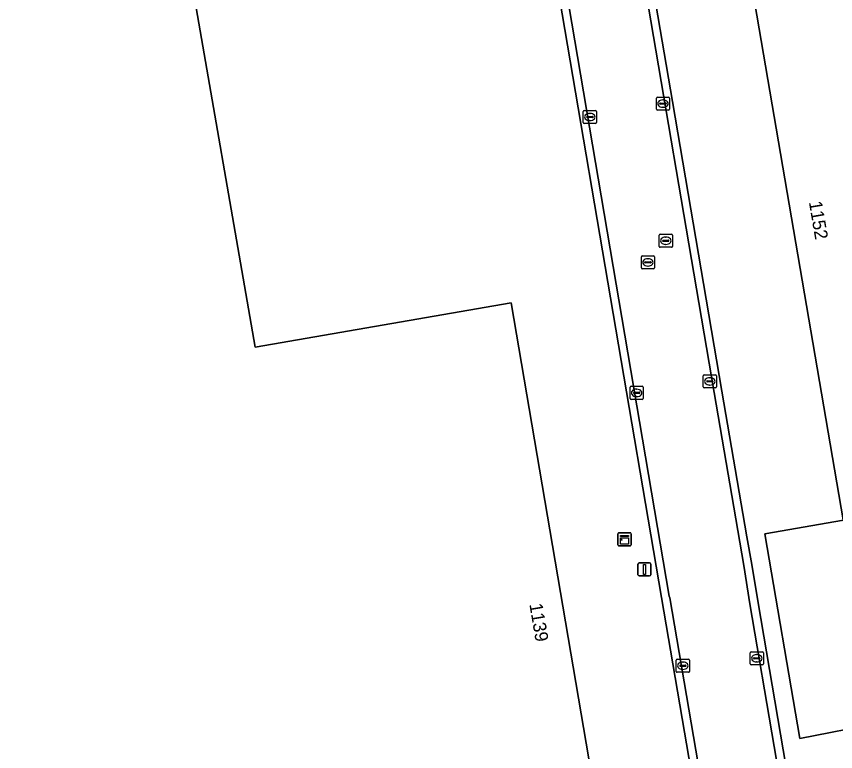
# Model space of a CAD drawing. Extents: x 154324 to 155744, y 382937 to 384188.
# Drawn here: x 154819.6 to 154882.3, y 383713.4 to 383769.7 of the extents above; entities that cross this region are included whole.
import ezdxf

# ---------------------------------------------------------------- set-up
doc = ezdxf.new("R2010")
doc.units = 0
for name, color, linetype in [('IMGEO_Kast', 7, 'Continuous'), ('IMGEO_Kolk', 7, 'Continuous'), ('IMGEO_Lichtmast', 7, 'Continuous'), ('IMGEO_Pand', 7, 'Continuous'), ('IMGEO_Pand_nummerreeks', 7, 'Continuous'), ('IMGEO_Parkeervlak_open', 7, 'Continuous'), ('IMGEO_Rijbaan_lokaal_gesloten', 7, 'Continuous'), ('IMGEO_Rijbaan_lokaal_open', 7, 'Continuous'), ('IMGEO_Rioolput', 7, 'Continuous'), ('IMGEO_Voetpad_open', 7, 'Continuous')]:
    doc.layers.add(name, color=color, linetype=linetype)

msp = doc.modelspace()

# ---------------------------------------------------------------- linework, layer by layer
at = {"layer": 'IMGEO_Kast'}
for p, q in [((154865.711, 383730.124), (154866.552, 383730.124)), ((154866.552, 383730.124), (154865.711, 383730.124)), ((154865.636, 383729.199), (154865.636, 383730.04)), ((154865.636, 383730.04), (154865.636, 383729.199)), ((154866.636, 383730.049), (154866.636, 383729.208)), ((154866.636, 383729.208), (154866.636, 383730.049)), ((154866.561, 383729.124), (154865.72, 383729.124)), ((154865.72, 383729.124), (154866.561, 383729.124))]:
    msp.add_line(p, q, dxfattribs=at)
for points in [[(154865.831, 383729.914), (154866.431, 383729.914), (154866.431, 383729.829), (154865.831, 383729.829), (154865.831, 383729.914)], [(154865.831, 383729.739), (154866.431, 383729.739), (154866.431, 383729.25), (154865.831, 383729.25), (154865.831, 383729.739)]]:
    msp.add_lwpolyline(points, dxfattribs=at)
msp.add_circle((154865.915, 383729.588), 0.0377, dxfattribs=at)
for centre, start, end in [((154865.714, 383730.046), 92.4484, 184.28452), ((154865.714, 383730.046), 92.4484, 184.28452), ((154866.558, 383730.046), 2.4484, 94.28452), ((154866.558, 383730.046), 2.4484, 94.28452), ((154865.714, 383729.202), 182.4484, 274.28452), ((154865.714, 383729.202), 182.4484, 274.28452), ((154866.558, 383729.202), 272.4484, 4.28452), ((154866.558, 383729.202), 272.4484, 4.28452)]:
    msp.add_arc(centre, 0.0779, start, end, dxfattribs=at)
at = {"layer": 'IMGEO_Kolk'}
for p, q in [((154868.575, 383762.549), (154868.575, 383763.401)), ((154868.65, 383763.475), (154869.502, 383763.475)), ((154869.576, 383763.401), (154869.576, 383762.549)), ((154868.834, 383762.969), (154868.834, 383762.981)), ((154869.272, 383762.932), (154868.874, 383762.932)), ((154868.877, 383763.018), (154869.275, 383763.018)), ((154869.086, 383762.695), (154869.061, 383762.695)), ((154869.063, 383763.255), (154869.088, 383763.255)), ((154869.318, 383762.981), (154869.318, 383762.969)), ((154862.984, 383761.524), (154862.984, 383762.376)), ((154863.059, 383762.45), (154863.911, 383762.45)), ((154863.472, 383762.23), (154863.497, 383762.23)), ((154863.985, 383762.376), (154863.985, 383761.524)), ((154869.502, 383762.475), (154868.65, 383762.475)), ((154863.911, 383761.45), (154863.059, 383761.45)), ((154863.243, 383761.944), (154863.243, 383761.956)), ((154863.681, 383761.907), (154863.283, 383761.907)), ((154863.286, 383761.993), (154863.684, 383761.993)), ((154863.495, 383761.67), (154863.47, 383761.67)), ((154863.727, 383761.956), (154863.727, 383761.944)), ((154872.164, 383741.281), (154872.164, 383742.133)), ((154872.239, 383742.207), (154873.091, 383742.207)), ((154872.652, 383741.987), (154872.677, 383741.987)), ((154873.165, 383742.133), (154873.165, 383741.281)), ((154872.423, 383741.701), (154872.423, 383741.713)), ((154872.861, 383741.664), (154872.463, 383741.664)), ((154872.466, 383741.75), (154872.864, 383741.75)), ((154872.675, 383741.427), (154872.65, 383741.427)), ((154872.907, 383741.713), (154872.907, 383741.701)), ((154866.57, 383740.405), (154866.57, 383741.257)), ((154866.645, 383741.331), (154867.497, 383741.331)), ((154866.829, 383740.825), (154866.829, 383740.837)), ((154867.267, 383740.788), (154866.869, 383740.788)), ((154866.872, 383740.874), (154867.27, 383740.874)), ((154867.058, 383741.111), (154867.083, 383741.111)), ((154867.313, 383740.837), (154867.313, 383740.825)), ((154867.571, 383741.257), (154867.571, 383740.405)), ((154873.091, 383741.207), (154872.239, 383741.207)), ((154867.497, 383740.331), (154866.645, 383740.331)), ((154867.081, 383740.551), (154867.056, 383740.551)), ((154875.756, 383720.087), (154875.756, 383720.939)), ((154875.831, 383721.013), (154876.683, 383721.013)), ((154876.244, 383720.793), (154876.269, 383720.793)), ((154876.757, 383720.939), (154876.757, 383720.087)), ((154870.098, 383719.512), (154870.098, 383720.364)), ((154870.173, 383720.438), (154871.025, 383720.438)), ((154870.586, 383720.218), (154870.611, 383720.218)), ((154871.099, 383720.364), (154871.099, 383719.512)), ((154876.015, 383720.507), (154876.015, 383720.519)), ((154876.453, 383720.47), (154876.055, 383720.47)), ((154876.058, 383720.556), (154876.456, 383720.556)), ((154876.267, 383720.233), (154876.242, 383720.233)), ((154876.499, 383720.519), (154876.499, 383720.507)), ((154871.025, 383719.438), (154870.173, 383719.438)), ((154870.357, 383719.932), (154870.357, 383719.944)), ((154870.795, 383719.895), (154870.397, 383719.895)), ((154870.4, 383719.981), (154870.798, 383719.981)), ((154870.609, 383719.658), (154870.584, 383719.658)), ((154870.841, 383719.944), (154870.841, 383719.932)), ((154876.683, 383720.013), (154875.831, 383720.013))]:
    msp.add_line(p, q, dxfattribs=at)
for points in [[(154868.575, 383762.549), (154868.575, 383763.401)], [(154868.65, 383763.475), (154869.502, 383763.475)], [(154869.576, 383763.401), (154869.576, 383762.549)], [(154862.984, 383761.524), (154862.984, 383762.376)], [(154863.059, 383762.45), (154863.911, 383762.45)], [(154863.985, 383762.376), (154863.985, 383761.524)], [(154869.502, 383762.475), (154868.65, 383762.475)], [(154863.911, 383761.45), (154863.059, 383761.45)], [(154872.164, 383741.281), (154872.164, 383742.133)], [(154872.239, 383742.207), (154873.091, 383742.207)], [(154873.165, 383742.133), (154873.165, 383741.281)], [(154866.57, 383740.405), (154866.57, 383741.257)], [(154866.645, 383741.331), (154867.497, 383741.331)], [(154867.571, 383741.257), (154867.571, 383740.405)], [(154873.091, 383741.207), (154872.239, 383741.207)], [(154867.497, 383740.331), (154866.645, 383740.331)], [(154875.756, 383720.087), (154875.756, 383720.939)], [(154875.831, 383721.013), (154876.683, 383721.013)], [(154876.757, 383720.939), (154876.757, 383720.087)], [(154870.098, 383719.512), (154870.098, 383720.364)], [(154870.173, 383720.438), (154871.025, 383720.438)], [(154871.099, 383720.364), (154871.099, 383719.512)], [(154871.025, 383719.438), (154870.173, 383719.438)], [(154876.683, 383720.013), (154875.831, 383720.013)]]:
    msp.add_lwpolyline(points, dxfattribs=at)
for centre, radius, start, end in [((154868.652, 383763.399), 0.0765, 91.55205, 178.44795), ((154868.652, 383763.399), 0.0765, 91.55205, 178.44795), ((154869.5, 383763.399), 0.0765, 1.55205, 88.44795), ((154869.5, 383763.399), 0.0765, 1.55205, 88.44795), ((154868.874, 383762.978), 0.0403, 85.87752, 175.75265), ((154868.871, 383762.968), 0.0366, 178.93798, 274.71019), ((154869.275, 383762.975), 0.043, 264.86636, 352.45326), ((154869.279, 383762.98), 0.0386, 1.73085, 96.63898), ((154863.061, 383762.374), 0.0765, 91.55205, 178.44795), ((154863.061, 383762.374), 0.0765, 91.55205, 178.44795), ((154863.909, 383762.374), 0.0765, 1.55205, 88.44795), ((154863.909, 383762.374), 0.0765, 1.55205, 88.44795), ((154868.652, 383762.551), 0.0765, 181.55205, 268.44795), ((154868.652, 383762.551), 0.0765, 181.55205, 268.44795), ((154869.5, 383762.551), 0.0765, 271.55205, 358.44795), ((154869.5, 383762.551), 0.0765, 271.55205, 358.44795), ((154863.061, 383761.526), 0.0765, 181.55205, 268.44795), ((154863.061, 383761.526), 0.0765, 181.55205, 268.44795), ((154863.283, 383761.953), 0.0403, 85.87752, 175.75265), ((154863.28, 383761.943), 0.0366, 178.93798, 274.71019), ((154863.684, 383761.95), 0.043, 264.86636, 352.45326), ((154863.688, 383761.955), 0.0386, 1.73085, 96.63898), ((154863.909, 383761.526), 0.0765, 271.55205, 358.44795), ((154863.909, 383761.526), 0.0765, 271.55205, 358.44795), ((154872.241, 383742.131), 0.0765, 91.55205, 178.44795), ((154872.241, 383742.131), 0.0765, 91.55205, 178.44795), ((154873.089, 383742.131), 0.0765, 1.55205, 88.44795), ((154873.089, 383742.131), 0.0765, 1.55205, 88.44795), ((154872.463, 383741.71), 0.0403, 85.87752, 175.75265), ((154872.46, 383741.7), 0.0366, 178.93798, 274.71019), ((154872.864, 383741.707), 0.043, 264.86636, 352.45326), ((154872.868, 383741.712), 0.0386, 1.73085, 96.63898), ((154866.647, 383741.255), 0.0765, 91.55205, 178.44795), ((154866.647, 383741.255), 0.0765, 91.55205, 178.44795), ((154866.869, 383740.834), 0.0403, 85.87752, 175.75265), ((154866.866, 383740.824), 0.0366, 178.93798, 274.71019), ((154867.27, 383740.831), 0.043, 264.86636, 352.45326), ((154867.274, 383740.836), 0.0386, 1.73085, 96.63898), ((154867.495, 383741.255), 0.0765, 1.55205, 88.44795), ((154867.495, 383741.255), 0.0765, 1.55205, 88.44795), ((154872.241, 383741.283), 0.0765, 181.55205, 268.44795), ((154872.241, 383741.283), 0.0765, 181.55205, 268.44795), ((154873.089, 383741.283), 0.0765, 271.55205, 358.44795), ((154873.089, 383741.283), 0.0765, 271.55205, 358.44795), ((154866.647, 383740.407), 0.0765, 181.55205, 268.44795), ((154866.647, 383740.407), 0.0765, 181.55205, 268.44795), ((154867.495, 383740.407), 0.0765, 271.55205, 358.44795), ((154867.495, 383740.407), 0.0765, 271.55205, 358.44795), ((154875.833, 383720.937), 0.0765, 91.55205, 178.44795), ((154875.833, 383720.937), 0.0765, 91.55205, 178.44795), ((154876.681, 383720.937), 0.0765, 1.55205, 88.44795), ((154876.681, 383720.937), 0.0765, 1.55205, 88.44795), ((154870.175, 383720.362), 0.0765, 91.55205, 178.44795), ((154870.175, 383720.362), 0.0765, 91.55205, 178.44795), ((154871.023, 383720.362), 0.0765, 1.55205, 88.44795), ((154871.023, 383720.362), 0.0765, 1.55205, 88.44795), ((154875.833, 383720.089), 0.0765, 181.55205, 268.44795), ((154875.833, 383720.089), 0.0765, 181.55205, 268.44795), ((154876.055, 383720.516), 0.0403, 85.87752, 175.75265), ((154876.052, 383720.506), 0.0366, 178.93798, 274.71019), ((154876.456, 383720.513), 0.043, 264.86636, 352.45326), ((154876.46, 383720.518), 0.0386, 1.73085, 96.63898), ((154876.681, 383720.089), 0.0765, 271.55205, 358.44795), ((154876.681, 383720.089), 0.0765, 271.55205, 358.44795), ((154870.175, 383719.514), 0.0765, 181.55205, 268.44795), ((154870.175, 383719.514), 0.0765, 181.55205, 268.44795), ((154870.397, 383719.941), 0.0403, 85.87752, 175.75265), ((154870.394, 383719.931), 0.0366, 178.93798, 274.71019), ((154870.798, 383719.938), 0.043, 264.86636, 352.45326), ((154870.802, 383719.943), 0.0386, 1.73085, 96.63898), ((154871.023, 383719.514), 0.0765, 271.55205, 358.44795), ((154871.023, 383719.514), 0.0765, 271.55205, 358.44795)]:
    msp.add_arc(centre, radius, start, end, dxfattribs=at)
for centre, major_axis, ratio, start_param, end_param in [((154869.062, 383762.975), (-0.387, 0.002), 0.722429, 4.712389, 7.853982), ((154869.087, 383762.975), (-0.39, 0.002), 0.717154, 1.570796, 4.712389), ((154863.471, 383761.95), (-0.387, 0.002), 0.722429, 4.712389, 7.853982), ((154863.496, 383761.95), (-0.39, 0.002), 0.717154, 1.570796, 4.712389), ((154872.651, 383741.707), (-0.387, 0.002), 0.722429, 4.712389, 7.853982), ((154872.676, 383741.707), (-0.39, 0.002), 0.717154, 1.570796, 4.712389), ((154867.057, 383740.831), (-0.387, 0.002), 0.722429, 4.712389, 7.853982), ((154867.082, 383740.831), (-0.39, 0.002), 0.717154, 1.570796, 4.712389), ((154876.243, 383720.513), (-0.387, 0.002), 0.722429, 4.712389, 7.853982), ((154876.268, 383720.513), (-0.39, 0.002), 0.717154, 1.570796, 4.712389), ((154870.585, 383719.938), (-0.387, 0.002), 0.722429, 4.712389, 7.853982), ((154870.61, 383719.938), (-0.39, 0.002), 0.717154, 1.570796, 4.712389)]:
    msp.add_ellipse(centre, major_axis=major_axis, ratio=ratio, start_param=start_param, end_param=end_param, dxfattribs=at)
at = {"layer": 'IMGEO_Lichtmast'}
for p, q in [((154867.168, 383726.911), (154867.168, 383727.711)), ((154867.168, 383727.711), (154867.168, 383726.911)), ((154867.268, 383727.811), (154868.058, 383727.811)), ((154868.058, 383727.811), (154867.268, 383727.811)), ((154868.158, 383727.711), (154868.158, 383726.911)), ((154868.158, 383726.911), (154868.158, 383727.711)), ((154868.058, 383726.811), (154867.268, 383726.811)), ((154867.268, 383726.811), (154868.058, 383726.811))]:
    msp.add_line(p, q, dxfattribs=at)
msp.add_lwpolyline([(154867.588, 383727.686), (154867.738, 383727.686), (154867.738, 383726.936), (154867.588, 383726.936), (154867.588, 383727.686)], dxfattribs=at)
for centre, start, end in [((154867.268, 383727.711), 90, 180), ((154867.268, 383727.711), 90, 180), ((154868.058, 383727.711), 0, 90), ((154868.058, 383727.711), 360, 90), ((154867.268, 383726.911), 180, 270), ((154867.268, 383726.911), 180, 270), ((154868.058, 383726.911), 270, 0), ((154868.058, 383726.911), 270, 0)]:
    msp.add_arc(centre, 0.1, start, end, dxfattribs=at)
at = {"layer": 'IMGEO_Pand'}
for points in [[(154837.735, 383816.061), (154769.16, 383784.679), (154787.882, 383674.892), (154867.567, 383688.391), (154857.459, 383747.727), (154837.877, 383744.339)], [(154837.877, 383744.339), (154832.77, 383773.851), (154852.427, 383777.261), (154848.68, 383799.111), (154846.651, 383810.938)]]:
    msp.add_lwpolyline(points, dxfattribs=at)
msp.add_lwpolyline([(154925.991, 383785.242), (154875.097, 383776.585), (154875.115, 383776.481), (154882.872, 383731.113), (154904.981, 383734.884), (154933.724, 383739.787)], close=True, dxfattribs=at)
at = {"layer": 'IMGEO_Parkeervlak_open'}
msp.add_lwpolyline([(154846.651, 383810.938), (154848.68, 383799.111), (154852.427, 383777.261), (154832.77, 383773.851), (154837.877, 383744.339), (154857.459, 383747.727), (154867.567, 383688.391), (154870.939, 383668.598), (154878.393, 383669.904), (154868.954, 383725.158), (154857.871, 383790.412)], dxfattribs=at)
at = {"layer": 'IMGEO_Rijbaan_lokaal_gesloten'}
for points in [[(154875.734, 383724.688), (154875.261, 383727.607), (154872.994, 383740.868), (154860.592, 383813.666), (154859.21, 383821.776)], [(154854.425, 383814.31), (154854.653, 383812.991), (154854.813, 383812.024), (154858.483, 383790.497), (154869.559, 383725.258), (154869.596, 383725.133), (154932.04, 383358.964), (154933.662, 383349.45), (154956.051, 383217.962), (154957.681, 383208.024), (154958.22, 383204.737)], [(154961.836, 383219.4), (154937.891, 383359.922), (154875.734, 383724.688)]]:
    msp.add_lwpolyline(points, dxfattribs=at)
at = {"layer": 'IMGEO_Rijbaan_lokaal_open'}
for points in [[(154886.005, 383668.098), (154882.999, 383685.742), (154876.351, 383724.763), (154875.865, 383727.687), (154875.499, 383729.815), (154873.585, 383740.95), (154869.805, 383763.145), (154867.747, 383775.228), (154861.316, 383812.985), (154859.633, 383822.862)], [(154859.21, 383821.776), (154860.592, 383813.666), (154872.994, 383740.868), (154875.261, 383727.607), (154875.734, 383724.688), (154937.891, 383359.922), (154938.491, 383360.02), (154937.698, 383364.674), (154936.71, 383370.477), (154936.699, 383370.542), (154936.688, 383370.604), (154886.005, 383668.098)], [(154853.936, 383813.593), (154856.176, 383800.396), (154857.871, 383790.412), (154868.954, 383725.158), (154878.393, 383669.904), (154880.297, 383658.755), (154880.326, 383658.587), (154931.446, 383358.867), (154932.04, 383358.964), (154869.596, 383725.133), (154869.559, 383725.258), (154858.483, 383790.497), (154854.813, 383812.024), (154854.653, 383812.991), (154854.425, 383814.31)]]:
    msp.add_lwpolyline(points, dxfattribs=at)
at = {"layer": 'IMGEO_Rioolput'}
for p, q in [((154868.795, 383752.048), (154868.795, 383752.9)), ((154868.87, 383752.974), (154869.722, 383752.974)), ((154869.283, 383752.754), (154869.308, 383752.754)), ((154869.796, 383752.9), (154869.796, 383752.048)), ((154869.054, 383752.468), (154869.054, 383752.48)), ((154869.492, 383752.431), (154869.094, 383752.431)), ((154869.097, 383752.517), (154869.495, 383752.517)), ((154869.306, 383752.194), (154869.281, 383752.194)), ((154869.538, 383752.48), (154869.538, 383752.468)), ((154869.722, 383751.974), (154868.87, 383751.974)), ((154867.426, 383750.392), (154867.426, 383751.244)), ((154867.501, 383751.318), (154868.353, 383751.318)), ((154867.685, 383750.812), (154867.685, 383750.824)), ((154868.123, 383750.775), (154867.725, 383750.775)), ((154867.728, 383750.861), (154868.126, 383750.861)), ((154867.914, 383751.098), (154867.939, 383751.098)), ((154868.169, 383750.824), (154868.169, 383750.812)), ((154868.427, 383751.244), (154868.427, 383750.392)), ((154868.353, 383750.318), (154867.501, 383750.318)), ((154867.937, 383750.538), (154867.912, 383750.538))]:
    msp.add_line(p, q, dxfattribs=at)
for points in [[(154868.795, 383752.048), (154868.795, 383752.9)], [(154868.87, 383752.974), (154869.722, 383752.974)], [(154869.796, 383752.9), (154869.796, 383752.048)], [(154869.722, 383751.974), (154868.87, 383751.974)], [(154867.426, 383750.392), (154867.426, 383751.244)], [(154867.501, 383751.318), (154868.353, 383751.318)], [(154868.427, 383751.244), (154868.427, 383750.392)], [(154868.353, 383750.318), (154867.501, 383750.318)]]:
    msp.add_lwpolyline(points, dxfattribs=at)
for centre, radius, start, end in [((154868.872, 383752.898), 0.0765, 91.55205, 178.44795), ((154868.872, 383752.898), 0.0765, 91.55205, 178.44795), ((154869.72, 383752.898), 0.0765, 1.55205, 88.44795), ((154869.72, 383752.898), 0.0765, 1.55205, 88.44795), ((154868.872, 383752.05), 0.0765, 181.55205, 268.44795), ((154868.872, 383752.05), 0.0765, 181.55205, 268.44795), ((154869.094, 383752.477), 0.0403, 85.87752, 175.75265), ((154869.091, 383752.467), 0.0366, 178.93798, 274.71019), ((154869.495, 383752.474), 0.043, 264.86636, 352.45326), ((154869.499, 383752.479), 0.0386, 1.73085, 96.63898), ((154869.72, 383752.05), 0.0765, 271.55205, 358.44795), ((154869.72, 383752.05), 0.0765, 271.55205, 358.44795), ((154867.503, 383751.242), 0.0765, 91.55205, 178.44795), ((154867.503, 383751.242), 0.0765, 91.55205, 178.44795), ((154867.725, 383750.821), 0.0403, 85.87752, 175.75265), ((154867.722, 383750.811), 0.0366, 178.93798, 274.71019), ((154868.126, 383750.818), 0.043, 264.86636, 352.45326), ((154868.13, 383750.823), 0.0386, 1.73085, 96.63898), ((154868.351, 383751.242), 0.0765, 1.55205, 88.44795), ((154868.351, 383751.242), 0.0765, 1.55205, 88.44795), ((154867.503, 383750.394), 0.0765, 181.55205, 268.44795), ((154867.503, 383750.394), 0.0765, 181.55205, 268.44795), ((154868.351, 383750.394), 0.0765, 271.55205, 358.44795), ((154868.351, 383750.394), 0.0765, 271.55205, 358.44795)]:
    msp.add_arc(centre, radius, start, end, dxfattribs=at)
for centre, major_axis, ratio, start_param, end_param in [((154869.282, 383752.474), (-0.387, 0.002), 0.722429, 4.712389, 7.853982), ((154869.307, 383752.474), (-0.39, 0.002), 0.717154, 1.570796, 4.712389), ((154867.913, 383750.818), (-0.387, 0.002), 0.722429, 4.712389, 7.853982), ((154867.938, 383750.818), (-0.39, 0.002), 0.717154, 1.570796, 4.712389)]:
    msp.add_ellipse(centre, major_axis=major_axis, ratio=ratio, start_param=start_param, end_param=end_param, dxfattribs=at)
at = {"layer": 'IMGEO_Voetpad_open'}
for points in [[(154885.53, 383715.542), (154879.545, 383714.381), (154876.862, 383730.049), (154882.878, 383731.08), (154882.872, 383731.113), (154875.115, 383776.481), (154867.747, 383775.228), (154869.805, 383763.145), (154873.585, 383740.95), (154875.499, 383729.815), (154875.865, 383727.687), (154876.351, 383724.763), (154882.999, 383685.742), (154886.005, 383668.098), (154895.235, 383669.681), (154892.427, 383686.211), (154890.574, 383685.895)], [(154883.053, 383730.038), (154883.047, 383730.075), (154882.878, 383731.08), (154876.862, 383730.049), (154879.545, 383714.381), (154885.53, 383715.542)]]:
    msp.add_lwpolyline(points, close=True, dxfattribs=at)

# ---------------------------------------------------------------- texts
at = {"layer": 'IMGEO_Pand_nummerreeks'}
for s, rotation, p in [('1152', 279.70569, (154880.235, 383755.434)), ('1139', 279.66559, (154858.855, 383724.646))]:
    msp.add_text(s, height=1, rotation=rotation, dxfattribs=at).set_placement(p)

doc.saveas('drawing.dxf')
